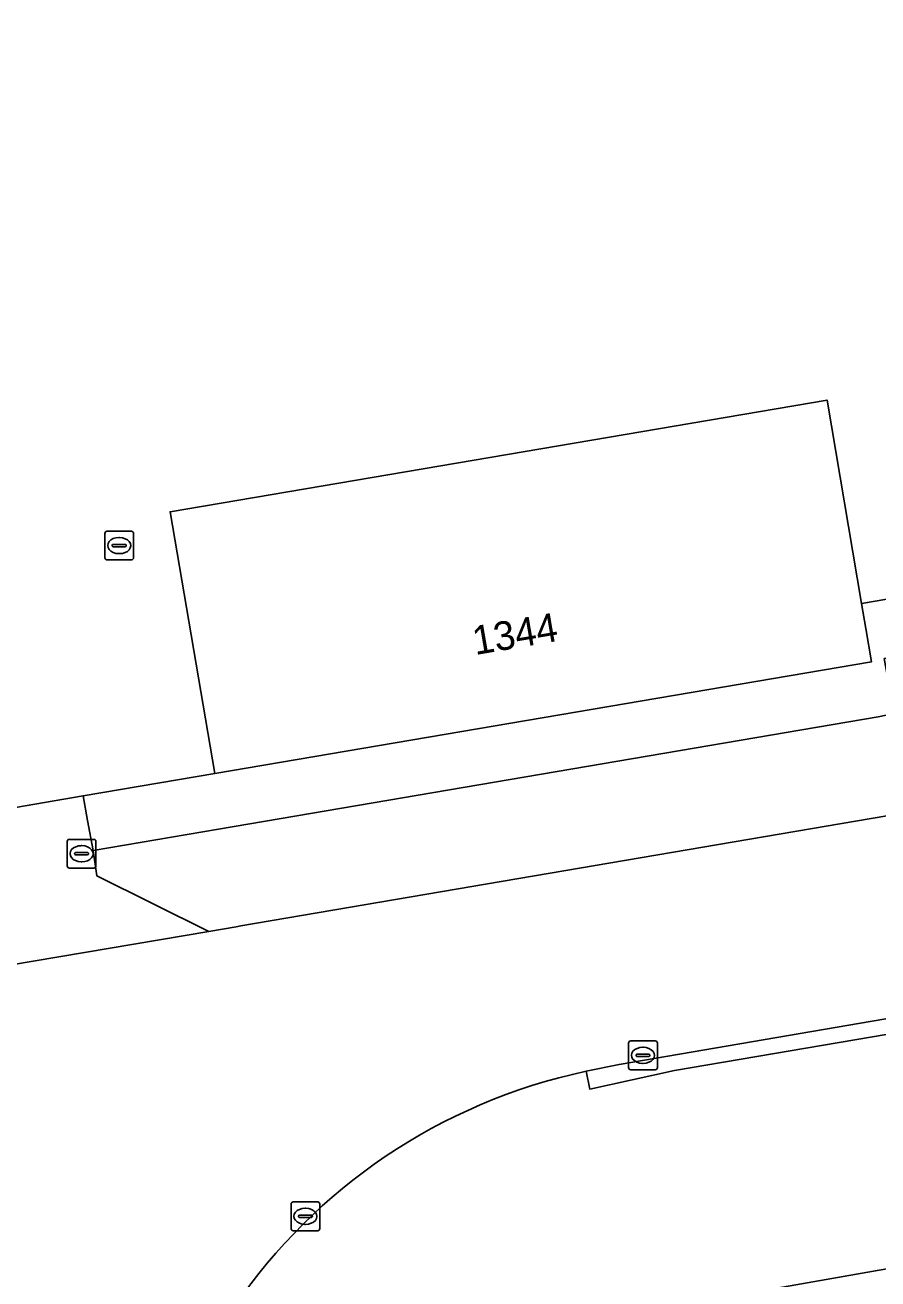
# Model space of a CAD drawing. Extents: x 154324 to 155744, y 382937 to 384188.
# Drawn here: x 154559.19 to 154588.89, y 383381.8 to 383425.49 of the extents above; entities that cross this region are included whole.
import ezdxf

# ---------------------------------------------------------------- set-up
doc = ezdxf.new("R2010")
doc.units = 0
for name, color, linetype in [('IMGEO_Erf', 7, 'Continuous'), ('IMGEO_Groenvoorziening', 7, 'Continuous'), ('IMGEO_Kolk', 7, 'Continuous'), ('IMGEO_Muur', 7, 'Continuous'), ('IMGEO_Pand', 7, 'Continuous'), ('IMGEO_Pand_nummerreeks', 7, 'Continuous'), ('IMGEO_Pand_vergunning_verleend', 7, 'Continuous'), ('IMGEO_Rijbaan_lokaal_gesloten', 7, 'Continuous'), ('IMGEO_Rijbaan_lokaal_open', 7, 'Continuous'), ('IMGEO_Rioolput', 7, 'Continuous'), ('IMGEO_Voetpad_open', 7, 'Continuous')]:
    doc.layers.add(name, color=color, linetype=linetype)

msp = doc.modelspace()

# ---------------------------------------------------------------- linework, layer by layer
at = {"layer": 'IMGEO_Erf'}
msp.add_lwpolyline([(154492.683, 383386.971), (154528.142, 383392.978), (154527.999, 383393.734), (154528.785, 383393.883), (154528.931, 383393.112), (154542.493, 383395.409), (154561.213, 383398.637), (154565.793, 383399.416), (154564.243, 383408.533), (154587.12, 383412.421), (154588.324, 383405.334), (154619.127, 383410.609)], dxfattribs=at)
at = {"layer": 'IMGEO_Groenvoorziening'}
msp.add_lwpolyline([(154628.223, 383396.96), (154581.809, 383389.068), (154578.853, 383388.42), (154578.734, 383389.04)], dxfattribs=at)
msp.add_arc((154582.891, 383369.566), 19.913, 102.0491, 188.6839, dxfattribs=at)
at = {"layer": 'IMGEO_Kolk'}
for p, q in [((154560.658, 383396.193), (154560.658, 383397.045)), ((154560.733, 383397.119), (154561.585, 383397.119)), ((154561.146, 383396.899), (154561.171, 383396.899)), ((154561.659, 383397.045), (154561.659, 383396.193)), ((154560.917, 383396.613), (154560.917, 383396.625)), ((154561.355, 383396.576), (154560.957, 383396.576)), ((154560.96, 383396.662), (154561.358, 383396.662)), ((154561.401, 383396.625), (154561.401, 383396.613)), ((154561.585, 383396.119), (154560.733, 383396.119)), ((154561.169, 383396.339), (154561.144, 383396.339)), ((154580.208, 383389.167), (154580.208, 383390.019)), ((154580.283, 383390.093), (154581.135, 383390.093)), ((154580.696, 383389.873), (154580.721, 383389.873)), ((154581.209, 383390.019), (154581.209, 383389.167)), ((154580.467, 383389.587), (154580.467, 383389.599)), ((154580.905, 383389.55), (154580.507, 383389.55)), ((154580.51, 383389.636), (154580.908, 383389.636)), ((154580.951, 383389.599), (154580.951, 383389.587)), ((154581.135, 383389.093), (154580.283, 383389.093)), ((154580.719, 383389.313), (154580.694, 383389.313)), ((154568.453, 383383.558), (154568.453, 383384.41)), ((154568.528, 383384.484), (154569.38, 383384.484)), ((154568.941, 383384.264), (154568.966, 383384.264)), ((154569.454, 383384.41), (154569.454, 383383.558)), ((154568.712, 383383.978), (154568.712, 383383.99)), ((154569.15, 383383.941), (154568.752, 383383.941)), ((154568.755, 383384.027), (154569.153, 383384.027)), ((154568.964, 383383.704), (154568.939, 383383.704)), ((154569.196, 383383.99), (154569.196, 383383.978)), ((154569.38, 383383.484), (154568.528, 383383.484))]:
    msp.add_line(p, q, dxfattribs=at)
for points in [[(154560.658, 383396.193), (154560.658, 383397.045)], [(154560.733, 383397.119), (154561.585, 383397.119)], [(154561.659, 383397.045), (154561.659, 383396.193)], [(154561.585, 383396.119), (154560.733, 383396.119)], [(154580.208, 383389.167), (154580.208, 383390.019)], [(154580.283, 383390.093), (154581.135, 383390.093)], [(154581.209, 383390.019), (154581.209, 383389.167)], [(154581.135, 383389.093), (154580.283, 383389.093)], [(154568.453, 383383.558), (154568.453, 383384.41)], [(154568.528, 383384.484), (154569.38, 383384.484)], [(154569.454, 383384.41), (154569.454, 383383.558)], [(154569.38, 383383.484), (154568.528, 383383.484)]]:
    msp.add_lwpolyline(points, dxfattribs=at)
for centre, radius, start, end in [((154560.735, 383397.043), 0.0765, 91.552, 178.448), ((154560.735, 383397.043), 0.0765, 91.552, 178.448), ((154561.583, 383397.043), 0.0765, 1.552, 88.448), ((154561.583, 383397.043), 0.0765, 1.552, 88.448), ((154560.957, 383396.622), 0.0403, 85.8775, 175.7526), ((154560.954, 383396.612), 0.0366, 178.938, 274.7102), ((154561.358, 383396.619), 0.043, 264.8664, 352.4533), ((154561.362, 383396.624), 0.0386, 1.7309, 96.639), ((154560.735, 383396.195), 0.0765, 181.552, 268.448), ((154560.735, 383396.195), 0.0765, 181.552, 268.448), ((154561.583, 383396.195), 0.0765, 271.552, 358.448), ((154561.583, 383396.195), 0.0765, 271.552, 358.448), ((154580.285, 383390.017), 0.0765, 91.552, 178.448), ((154580.285, 383390.017), 0.0765, 91.552, 178.448), ((154581.133, 383390.017), 0.0765, 1.552, 88.448), ((154581.133, 383390.017), 0.0765, 1.552, 88.448), ((154580.507, 383389.596), 0.0403, 85.8775, 175.7526), ((154580.504, 383389.586), 0.0366, 178.938, 274.7102), ((154580.908, 383389.593), 0.043, 264.8664, 352.4533), ((154580.912, 383389.598), 0.0386, 1.7309, 96.639), ((154580.285, 383389.169), 0.0765, 181.552, 268.448), ((154580.285, 383389.169), 0.0765, 181.552, 268.448), ((154581.133, 383389.169), 0.0765, 271.552, 358.448), ((154581.133, 383389.169), 0.0765, 271.552, 358.448), ((154568.53, 383384.408), 0.0765, 91.552, 178.448), ((154568.53, 383384.408), 0.0765, 91.552, 178.448), ((154569.378, 383384.408), 0.0765, 1.552, 88.448), ((154569.378, 383384.408), 0.0765, 1.552, 88.448), ((154568.752, 383383.987), 0.0403, 85.8775, 175.7526), ((154568.749, 383383.977), 0.0366, 178.938, 274.7102), ((154569.153, 383383.984), 0.043, 264.8664, 352.4533), ((154569.157, 383383.989), 0.0386, 1.7309, 96.639), ((154568.53, 383383.56), 0.0765, 181.552, 268.448), ((154568.53, 383383.56), 0.0765, 181.552, 268.448), ((154569.378, 383383.56), 0.0765, 271.552, 358.448), ((154569.378, 383383.56), 0.0765, 271.552, 358.448)]:
    msp.add_arc(centre, radius, start, end, dxfattribs=at)
for centre, major_axis, ratio, start_param, end_param in [((154561.145, 383396.619), (-0.387, 0.002), 0.722429, 4.712389, 7.853982), ((154561.17, 383396.619), (-0.39, 0.002), 0.717154, 1.570796, 4.712389), ((154580.695, 383389.593), (-0.387, 0.002), 0.722429, 4.712389, 7.853982), ((154580.72, 383389.593), (-0.39, 0.002), 0.717154, 1.570796, 4.712389), ((154568.94, 383383.984), (-0.387, 0.002), 0.722429, 4.712389, 7.853982), ((154568.965, 383383.984), (-0.39, 0.002), 0.717154, 1.570796, 4.712389)]:
    msp.add_ellipse(centre, major_axis=major_axis, ratio=ratio, start_param=start_param, end_param=end_param, dxfattribs=at)
at = {"layer": 'IMGEO_Muur'}
msp.add_lwpolyline([(154619.127, 383410.609), (154588.324, 383405.334), (154588.471, 383404.469), (154588.669, 383403.305), (154565.793, 383399.416), (154561.213, 383398.637), (154561.368, 383397.779), (154561.557, 383396.732), (154565.932, 383397.477), (154588.899, 383401.391), (154589.456, 383401.5), (154589.111, 383403.417), (154620.536, 383408.912), (154629.486, 383420.57), (154620.479, 383473.443), (154607.809, 383547.76), (154607.773, 383547.785), (154593.424, 383558.018), (154532.899, 383547.825), (154466.047, 383536.26)], dxfattribs=at)
at = {"layer": 'IMGEO_Pand'}
msp.add_lwpolyline([(154588.324, 383405.334), (154587.12, 383412.421), (154564.243, 383408.533), (154565.793, 383399.416), (154588.669, 383403.305), (154588.471, 383404.469)], close=True, dxfattribs=at)
at = {"layer": 'IMGEO_Pand_vergunning_verleend'}
msp.add_lwpolyline([(154581.149, 383380.739), (154662.352, 383395.018), (154661.003, 383402.69), (154725.439, 383414.021), (154741.008, 383314.156), (154688.601, 383305.253), (154686.823, 383315.722), (154675.237, 383313.754), (154678.064, 383297.115), (154596.812, 383283.312)], close=True, dxfattribs=at)
at = {"layer": 'IMGEO_Rijbaan_lokaal_gesloten'}
for points in [[(154619.262, 383403.054), (154566.699, 383394.1), (154566.542, 383394.073), (154565.586, 383393.91), (154540.425, 383389.655), (154539.476, 383389.491), (154537.747, 383389.193), (154533.036, 383388.38), (154530.012, 383387.859), (154529.191, 383387.717), (154519.218, 383385.997), (154516.466, 383385.522), (154494.182, 383381.711)], [(154578.734, 383389.04), (154579.877, 383389.278), (154628.133, 383397.548)], [(154628.133, 383397.548), (154579.877, 383389.278), (154578.734, 383389.04), (154578.853, 383388.42), (154581.809, 383389.068), (154628.223, 383396.96)]]:
    msp.add_lwpolyline(points, dxfattribs=at)
msp.add_arc((154582.891, 383369.566), 19.913, 102.0491, 188.6839, dxfattribs=at)
at = {"layer": 'IMGEO_Rijbaan_lokaal_open'}
msp.add_lwpolyline([(154561.692, 383395.846), (154561.557, 383396.732), (154561.368, 383397.779), (154561.213, 383398.637), (154542.493, 383395.409), (154542.971, 383392.88), (154542.909, 383392.801), (154540.425, 383389.655), (154565.586, 383393.91)], close=True, dxfattribs=at)
at = {"layer": 'IMGEO_Rioolput'}
for p, q in [((154561.967, 383406.927), (154561.967, 383407.779)), ((154562.042, 383407.853), (154562.894, 383407.853)), ((154562.968, 383407.779), (154562.968, 383406.927)), ((154562.226, 383407.347), (154562.226, 383407.359)), ((154562.664, 383407.31), (154562.266, 383407.31)), ((154562.269, 383407.396), (154562.667, 383407.396)), ((154562.455, 383407.633), (154562.48, 383407.633)), ((154562.71, 383407.359), (154562.71, 383407.347)), ((154562.894, 383406.853), (154562.042, 383406.853)), ((154562.478, 383407.073), (154562.453, 383407.073))]:
    msp.add_line(p, q, dxfattribs=at)
for points in [[(154561.967, 383406.927), (154561.967, 383407.779)], [(154562.042, 383407.853), (154562.894, 383407.853)], [(154562.968, 383407.779), (154562.968, 383406.927)], [(154562.894, 383406.853), (154562.042, 383406.853)]]:
    msp.add_lwpolyline(points, dxfattribs=at)
for centre, radius, start, end in [((154562.044, 383407.777), 0.0765, 91.552, 178.448), ((154562.044, 383407.777), 0.0765, 91.552, 178.448), ((154562.892, 383407.777), 0.0765, 1.552, 88.448), ((154562.892, 383407.777), 0.0765, 1.552, 88.448), ((154562.266, 383407.356), 0.0403, 85.8775, 175.7526), ((154562.263, 383407.346), 0.0366, 178.938, 274.7102), ((154562.667, 383407.353), 0.043, 264.8664, 352.4533), ((154562.671, 383407.358), 0.0386, 1.7309, 96.639), ((154562.044, 383406.929), 0.0765, 181.552, 268.448), ((154562.044, 383406.929), 0.0765, 181.552, 268.448), ((154562.892, 383406.929), 0.0765, 271.552, 358.448), ((154562.892, 383406.929), 0.0765, 271.552, 358.448)]:
    msp.add_arc(centre, radius, start, end, dxfattribs=at)
for centre, major_axis, ratio, start_param, end_param in [((154562.454, 383407.353), (-0.387, 0.002), 0.722429, 4.712389, 7.853982), ((154562.479, 383407.353), (-0.39, 0.002), 0.717154, 1.570796, 4.712389)]:
    msp.add_ellipse(centre, major_axis=major_axis, ratio=ratio, start_param=start_param, end_param=end_param, dxfattribs=at)
at = {"layer": 'IMGEO_Voetpad_open'}
msp.add_lwpolyline([(154627.016, 383406.929), (154603.624, 383402.968), (154589.619, 383400.597), (154589.569, 383400.873), (154589.456, 383401.5), (154588.899, 383401.391), (154565.932, 383397.477), (154561.557, 383396.732), (154561.692, 383395.846), (154565.586, 383393.91), (154566.542, 383394.073), (154566.699, 383394.1), (154619.262, 383403.054)], dxfattribs=at)

# ---------------------------------------------------------------- texts
at = {"layer": 'IMGEO_Pand_nummerreeks'}
msp.add_text('1344', height=1, rotation=9.7476, dxfattribs=at).set_placement((154574.864, 383403.537))

doc.saveas('drawing.dxf')
